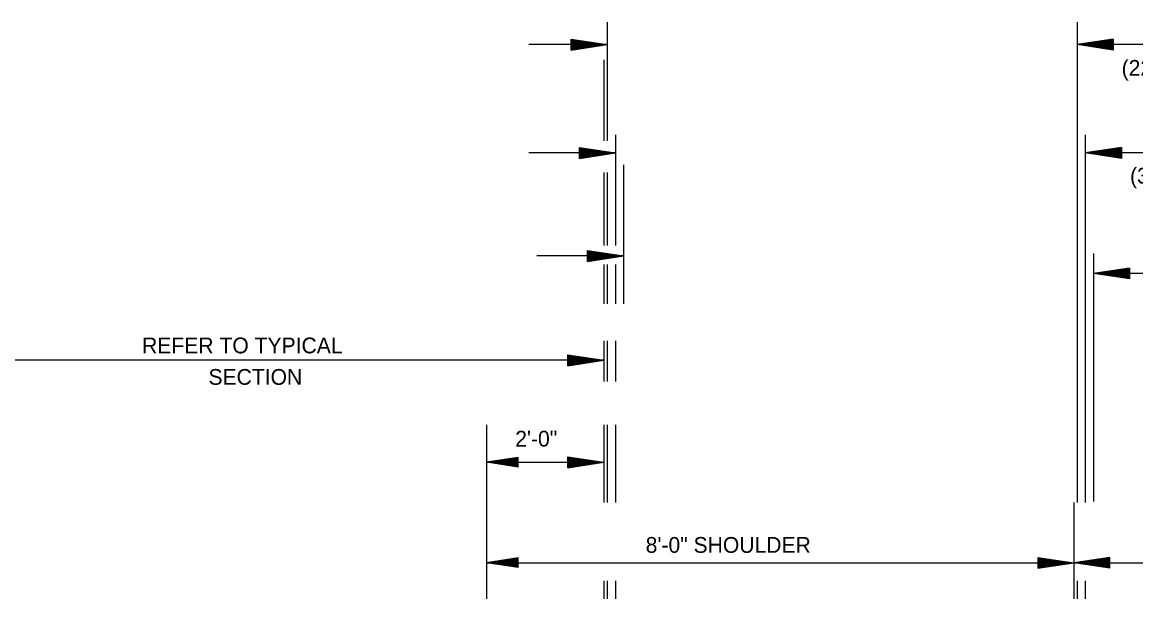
# Model space of a CAD drawing. Extents: x -2842 to 2681, y -2139 to 474.
# Drawn here: x -379 to 44.4, y -953.4 to -734.2 of the extents above; entities that cross this region are included whole.
import ezdxf

# ---------------------------------------------------------------- set-up
doc = ezdxf.new("R2010")
doc.units = 0
doc.layers.add('Default', color=7, linetype='Continuous')

msp = doc.modelspace()

# ---------------------------------------------------------------- linework, layer by layer
at = {"layer": 'Default'}
for p, q in [((-156.53, -734.21), (-156.53, -779.33)), ((22.18, -734.21), (22.18, -916.75)), ((-170.21, -740.68), (-156.53, -742.72)), ((-170.21, -744.78), (-170.21, -740.68)), ((35.88, -740.68), (22.18, -742.72)), ((35.88, -740.68), (35.88, -744.78)), ((-156.53, -742.72), (-186.38, -742.72)), ((-170.21, -741.01), (-158.8, -742.72)), ((-170.21, -741.36), (-161.16, -742.72)), ((-170.21, -741.69), (-163.45, -742.72)), ((-170.21, -742.08), (-165.77, -742.72)), ((-170.21, -742.39), (-168.04, -742.72)), ((-170.21, -744.78), (-156.53, -742.72)), ((-170.21, -743.4), (-165.77, -742.72)), ((-170.21, -744.09), (-161.16, -742.72)), ((-170.21, -744.43), (-158.8, -742.72)), ((-170.21, -743.73), (-163.45, -742.72)), ((-170.21, -743.05), (-168.04, -742.72)), ((35.88, -744.78), (22.18, -742.72)), ((248.47, -742.72), (22.18, -742.72)), ((35.88, -741.01), (24.45, -742.72)), ((35.88, -744.43), (24.45, -742.72)), ((35.88, -741.36), (26.82, -742.72)), ((35.88, -744.09), (26.82, -742.72)), ((35.88, -741.69), (29.1, -742.72)), ((35.88, -743.73), (29.1, -742.72)), ((35.88, -742.08), (31.42, -742.72)), ((35.88, -743.4), (31.42, -742.72)), ((35.88, -742.39), (33.69, -742.72)), ((35.88, -743.05), (33.69, -742.72)), ((-157.79, -748.5), (-157.79, -779.33)), ((-153.46, -777.05), (-153.46, -819.05)), ((25.25, -777.05), (25.25, -916.75)), ((-167.14, -781.85), (-153.46, -783.89)), ((-167.14, -785.95), (-167.14, -781.85)), ((-167.14, -782.18), (-155.72, -783.89)), ((-167.14, -782.54), (-158.07, -783.89)), ((-167.14, -782.86), (-160.34, -783.89)), ((-167.14, -783.24), (-162.67, -783.89)), ((38.95, -781.85), (25.25, -783.89)), ((38.95, -782.18), (27.56, -783.89)), ((38.95, -782.54), (29.89, -783.89)), ((38.95, -782.86), (32.17, -783.89)), ((38.95, -783.24), (34.49, -783.89)), ((38.95, -781.85), (38.95, -785.95)), ((-153.46, -783.89), (-186.38, -783.89)), ((-167.14, -783.57), (-164.96, -783.89)), ((-167.14, -785.95), (-153.46, -783.89)), ((-167.14, -784.58), (-162.67, -783.89)), ((-167.14, -785.26), (-158.07, -783.89)), ((-167.14, -785.61), (-155.72, -783.89)), ((-167.14, -784.92), (-160.34, -783.89)), ((-167.14, -784.2), (-164.96, -783.89)), ((38.95, -785.95), (25.25, -783.89)), ((247.77, -783.89), (25.25, -783.89)), ((38.95, -785.61), (27.56, -783.89)), ((38.95, -785.26), (29.89, -783.89)), ((38.95, -784.92), (32.17, -783.89)), ((38.95, -784.58), (34.49, -783.89)), ((38.95, -783.57), (36.78, -783.89)), ((38.95, -784.2), (36.78, -783.89)), ((-157.79, -791.33), (-157.79, -819.05)), ((-156.53, -791.33), (-156.53, -819.05)), ((-150.39, -788.47), (-150.39, -841.33)), ((-164.07, -821.03), (-150.39, -823.07)), ((-164.07, -825.13), (-164.07, -821.03)), ((-164.07, -821.36), (-152.65, -823.07)), ((-150.39, -823.07), (-183.31, -823.07)), ((-164.07, -821.72), (-155, -823.07)), ((-164.07, -822.04), (-157.27, -823.07)), ((-164.07, -822.42), (-159.6, -823.07)), ((-164.07, -822.75), (-161.89, -823.07)), ((-164.07, -825.13), (-150.39, -823.07)), ((-164.07, -823.76), (-159.6, -823.07)), ((-164.07, -824.44), (-155, -823.07)), ((-164.07, -824.79), (-152.65, -823.07)), ((-164.07, -824.1), (-157.27, -823.07)), ((-164.07, -823.38), (-161.89, -823.07)), ((28.32, -822.12), (28.32, -916.47)), ((-157.79, -826.33), (-157.79, -841.33)), ((-156.53, -826.33), (-156.53, -841.33)), ((-153.46, -826.33), (-153.46, -841.33)), ((42.02, -827.65), (28.32, -829.69)), ((42.02, -831.75), (28.32, -829.69)), ((250.84, -829.69), (28.32, -829.69)), ((42.02, -827.98), (30.63, -829.69)), ((42.02, -831.41), (30.63, -829.69)), ((42.02, -828.34), (32.96, -829.69)), ((42.02, -831.06), (32.96, -829.69)), ((42.02, -828.66), (35.24, -829.69)), ((42.02, -830.72), (35.24, -829.69)), ((42.02, -829.04), (37.56, -829.69)), ((42.02, -830.38), (37.56, -829.69)), ((42.02, -829.37), (39.85, -829.69)), ((42.02, -830), (39.85, -829.69)), ((42.02, -827.65), (42.02, -831.75)), ((-157.79, -855.29), (-157.79, -870.81)), ((-156.53, -855.29), (-156.53, -870.81)), ((-153.46, -855.29), (-153.46, -870.81)), ((-157.79, -862.72), (-414.12, -862.72)), ((-171.49, -860.68), (-157.79, -862.72)), ((-171.49, -864.78), (-171.49, -860.68)), ((-171.49, -861.01), (-160.06, -862.72)), ((-171.49, -861.37), (-162.43, -862.72)), ((-171.49, -861.7), (-164.72, -862.72)), ((-171.49, -862.07), (-167.03, -862.72)), ((-171.49, -862.4), (-169.31, -862.72)), ((-171.49, -864.78), (-157.79, -862.72)), ((-171.49, -863.41), (-167.03, -862.72)), ((-171.49, -864.1), (-162.43, -862.72)), ((-171.49, -864.44), (-160.06, -862.72)), ((-171.49, -863.74), (-164.72, -862.72)), ((-171.49, -863.05), (-169.31, -862.72)), ((-202.46, -887.24), (-202.46, -953.4)), ((-157.79, -887.24), (-157.79, -916.75)), ((-156.53, -887.24), (-156.53, -916.75)), ((-153.46, -887.24), (-153.46, -916.75)), ((-190.46, -899.73), (-202.46, -901.53)), ((-202.46, -901.53), (-157.79, -901.53)), ((-190.46, -903.33), (-202.46, -901.53)), ((-190.46, -900.03), (-200.46, -901.53)), ((-190.46, -903.03), (-200.46, -901.53)), ((-190.46, -900.34), (-198.39, -901.53)), ((-190.46, -902.72), (-198.39, -901.53)), ((-190.46, -900.64), (-196.39, -901.53)), ((-190.46, -902.42), (-196.39, -901.53)), ((-190.46, -900.94), (-194.36, -901.53)), ((-190.46, -902.11), (-194.36, -901.53)), ((-190.46, -901.25), (-192.36, -901.53)), ((-190.46, -901.81), (-192.36, -901.53)), ((-190.46, -903.33), (-190.46, -899.73)), ((-171.49, -899.49), (-157.79, -901.53)), ((-171.49, -903.59), (-171.49, -899.49)), ((-171.49, -899.82), (-160.06, -901.53)), ((-171.49, -900.18), (-162.43, -901.53)), ((-171.49, -900.51), (-164.72, -901.53)), ((-171.49, -900.88), (-167.03, -901.53)), ((-171.49, -901.21), (-169.31, -901.53)), ((-171.49, -903.59), (-157.79, -901.53)), ((-171.49, -902.22), (-167.03, -901.53)), ((-171.49, -902.91), (-162.43, -901.53)), ((-171.49, -903.25), (-160.06, -901.53)), ((-171.49, -902.55), (-164.72, -901.53)), ((-171.49, -901.86), (-169.31, -901.53)), ((20.9, -916.75), (20.9, -953.4)), ((-190.46, -937.9), (-202.46, -939.7)), ((-202.46, -939.7), (20.9, -939.7)), ((-190.46, -941.5), (-202.46, -939.7)), ((-190.46, -938.2), (-200.46, -939.7)), ((-190.46, -941.2), (-200.46, -939.7)), ((-190.46, -938.51), (-198.39, -939.7)), ((-190.46, -940.89), (-198.39, -939.7)), ((-190.46, -938.81), (-196.39, -939.7)), ((-190.46, -940.59), (-196.39, -939.7)), ((-190.46, -939.11), (-194.36, -939.7)), ((-190.46, -940.28), (-194.36, -939.7)), ((-190.46, -939.42), (-192.36, -939.7)), ((-190.46, -939.98), (-192.36, -939.7)), ((-190.46, -941.5), (-190.46, -937.9)), ((7.22, -937.66), (20.9, -939.7)), ((7.22, -937.66), (7.22, -941.76)), ((7.22, -937.99), (18.61, -939.7)), ((7.22, -938.35), (16.27, -939.7)), ((7.22, -938.68), (14, -939.7)), ((7.22, -939.05), (11.64, -939.7)), ((7.22, -939.38), (9.37, -939.7)), ((7.22, -941.76), (20.9, -939.7)), ((7.22, -940.39), (11.64, -939.7)), ((7.22, -941.08), (16.27, -939.7)), ((7.22, -941.42), (18.61, -939.7)), ((7.22, -940.72), (14, -939.7)), ((7.22, -940.03), (9.37, -939.7)), ((34.6, -937.66), (20.9, -939.7)), ((20.9, -939.7), (245.22, -939.7)), ((34.6, -941.76), (20.9, -939.7)), ((34.6, -937.99), (23.18, -939.7)), ((34.6, -941.42), (23.18, -939.7)), ((34.6, -938.35), (25.53, -939.7)), ((34.6, -941.08), (25.53, -939.7)), ((34.6, -938.68), (27.82, -939.7)), ((34.6, -940.72), (27.82, -939.7)), ((34.6, -939.05), (30.13, -939.7)), ((34.6, -940.39), (30.13, -939.7)), ((34.6, -939.38), (32.4, -939.7)), ((34.6, -940.03), (32.4, -939.7)), ((34.6, -941.76), (34.6, -937.66)), ((-157.79, -946.54), (-157.79, -953.4)), ((-156.53, -946.54), (-156.53, -953.4)), ((-153.46, -946.54), (-153.46, -953.4)), ((20.9, -946.54), (20.9, -953.4)), ((22.18, -946.54), (22.18, -953.4)), ((25.25, -946.54), (25.25, -953.4))]:
    msp.add_line(p, q, dxfattribs=at)

# ---------------------------------------------------------------- texts
for s, p in [('(220 LBS. PER SQ. YD.) & TACK COAT', (39.06, -754.56)), ('(330 LBS. PER SQ. YD.) & TACK COAT', (42.25, -795.55)), ('REFER TO TYPICAL', (-333.43, -860.09)), ('SECTION', (-308.19, -872.06)), ('2\'-0"', (-191.54, -895.54)), ('8\'-0" SHOULDER', (-141.93, -935.94))]:
    msp.add_text(s, height=6, dxfattribs=at).set_placement(p)

doc.saveas('drawing.dxf')
